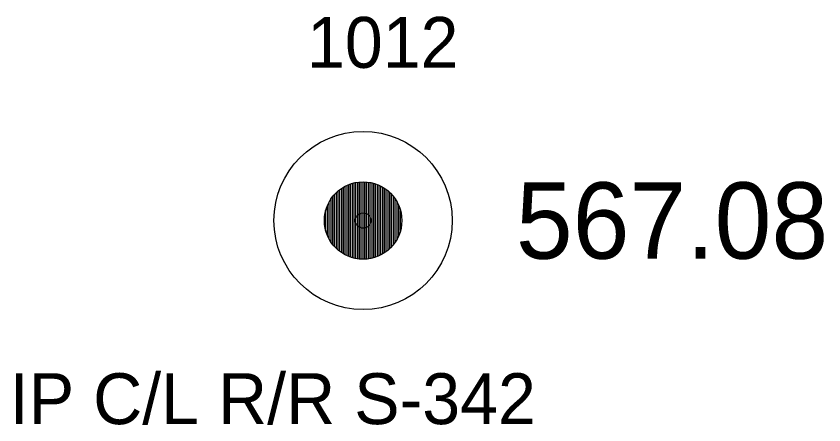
# Model space of a CAD drawing. Extents: x 1789242 to 1794757, y 908627 to 913936.
# Drawn here: x 1793397.27 to 1793413.14, y 913928.41 to 913936.44 of the extents above; entities that cross this region are included whole.
import ezdxf

# ---------------------------------------------------------------- set-up
doc = ezdxf.new("R2010")
doc.units = 0
for name, color, linetype in [('RD_EX_DV_Prop_txCode', 7, 'Continuous'), ('RD_EX_DV_PropPin', 7, 'Continuous'), ('RD_EX_TX_DV_Prop_ELEV', 7, 'Continuous'), ('RD_SMD_Locator', 7, 'Continuous')]:
    doc.layers.add(name, color=color, linetype=linetype)

msp = doc.modelspace()

# ---------------------------------------------------------------- linework, layer by layer
at = {"layer": 'RD_EX_DV_PropPin'}
for p, q in [((1793403.738, 913931.75), (1793403.738, 913933.101)), ((1793403.773, 913931.733), (1793403.773, 913933.118)), ((1793403.808, 913931.718), (1793403.808, 913933.133)), ((1793403.843, 913931.705), (1793403.843, 913933.146)), ((1793403.878, 913931.694), (1793403.878, 913933.157)), ((1793403.913, 913931.685), (1793403.913, 913933.166)), ((1793403.948, 913931.677), (1793403.948, 913933.173)), ((1793403.983, 913931.672), (1793403.983, 913933.179)), ((1793404.018, 913931.668), (1793404.018, 913933.183)), ((1793404.053, 913931.665), (1793404.053, 913933.186)), ((1793404.088, 913931.664), (1793404.088, 913933.186)), ((1793404.123, 913931.665), (1793404.123, 913933.186)), ((1793404.158, 913931.668), (1793404.158, 913933.183)), ((1793404.193, 913931.672), (1793404.193, 913933.179)), ((1793404.228, 913931.677), (1793404.228, 913933.173)), ((1793404.263, 913931.685), (1793404.263, 913933.166)), ((1793404.298, 913931.694), (1793404.298, 913933.157)), ((1793404.333, 913931.705), (1793404.333, 913933.146)), ((1793404.368, 913931.718), (1793404.368, 913933.133)), ((1793404.404, 913931.733), (1793404.404, 913933.118)), ((1793404.439, 913931.75), (1793404.439, 913933.101)), ((1793403.528, 913931.91), (1793403.528, 913932.94)), ((1793403.563, 913931.875), (1793403.563, 913932.976)), ((1793403.598, 913931.843), (1793403.598, 913933.008)), ((1793403.633, 913931.816), (1793403.633, 913933.035)), ((1793403.668, 913931.791), (1793403.668, 913933.06)), ((1793403.703, 913931.769), (1793403.703, 913933.082)), ((1793404.474, 913931.769), (1793404.474, 913933.082)), ((1793404.509, 913931.791), (1793404.509, 913933.06)), ((1793404.544, 913931.816), (1793404.544, 913933.035)), ((1793404.579, 913931.843), (1793404.579, 913933.008)), ((1793404.614, 913931.875), (1793404.614, 913932.976)), ((1793404.649, 913931.91), (1793404.649, 913932.94)), ((1793403.423, 913932.056), (1793403.423, 913932.795)), ((1793403.458, 913931.999), (1793403.458, 913932.852)), ((1793403.493, 913931.951), (1793403.493, 913932.9)), ((1793404.684, 913931.951), (1793404.684, 913932.9)), ((1793404.719, 913931.999), (1793404.719, 913932.852)), ((1793404.754, 913932.056), (1793404.754, 913932.795)), ((1793403.353, 913932.229), (1793403.353, 913932.622)), ((1793403.388, 913932.127), (1793403.388, 913932.723)), ((1793404.789, 913932.127), (1793404.789, 913932.723)), ((1793404.824, 913932.229), (1793404.824, 913932.622))]:
    msp.add_line(p, q, dxfattribs=at)
for radius in [1.75, 0.761]:
    msp.add_circle((1793404.088, 913932.425), radius, dxfattribs=at)
at = {"layer": 'RD_SMD_Locator'}
msp.add_circle((1793404.088, 913932.425), 0.15, dxfattribs=at)

# ---------------------------------------------------------------- texts
at = {"layer": 'RD_EX_DV_Prop_txCode'}
for s, p in [('1012', (1793402.986, 913935.425)), ('IP C/L R/R S-342', (1793397.151, 913928.425))]:
    msp.add_text(s, height=1, dxfattribs=at).set_placement(p)
at = {"layer": 'RD_EX_TX_DV_Prop_ELEV'}
msp.add_text('567.08', height=1.5, dxfattribs=at).set_placement((1793407.088, 913931.675))

doc.saveas('drawing.dxf')
